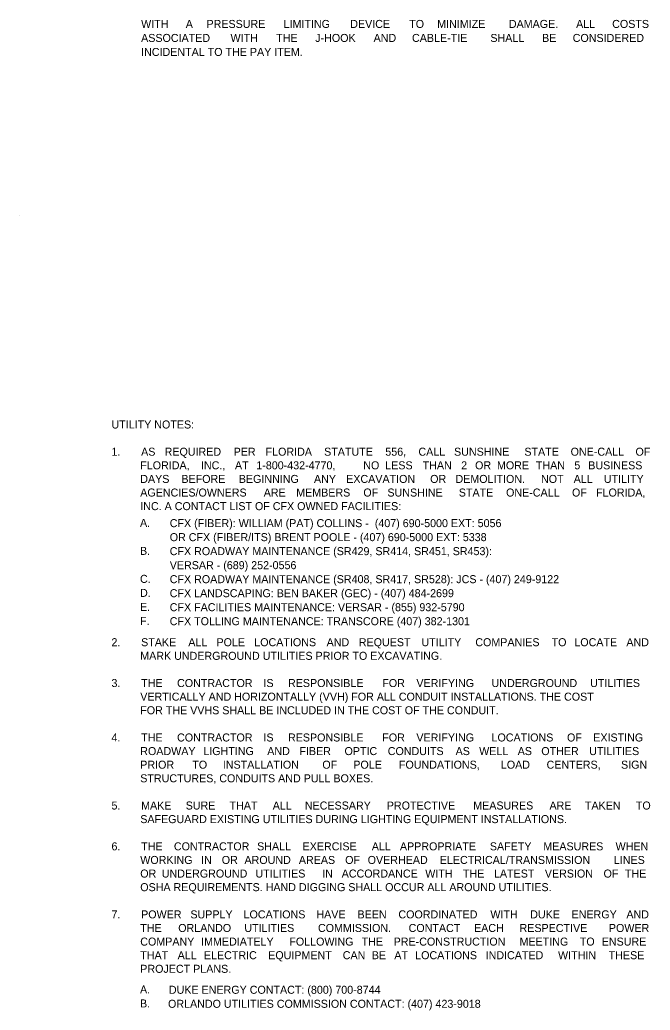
# Model space of a CAD drawing. Extents: x -55 to 2471539, y -90 to 3608906.
# Drawn here: x -54 to 497, y 1661 to 2527 of the extents above; entities that cross this region are included whole.
import ezdxf

# ---------------------------------------------------------------- set-up
doc = ezdxf.new("R2010")
doc.units = 0
doc.layers.add('TextMinor', color=7, linetype='Continuous')
doc.layers.add('XSCell', color=7, linetype='Continuous')

msp = doc.modelspace()

# ---------------------------------------------------------------- linework, layer by layer
at = {"layer": 'TextMinor'}
msp.add_line((-54.3, 2356.32), (-54.3, 2356.32), dxfattribs=at)

# ---------------------------------------------------------------- texts
at = {"layer": 'XSCell'}
for s, p in [('WITH ', (51.88, 2519.99)), ('A ', (90.93, 2519.99)), ('PRESSURE ', (109.08, 2519.99)), ('LIMITING ', (176.56, 2519.99)), ('DEVICE ', (234.88, 2519.99)), ('TO ', (286.48, 2519.99)), ('MINIMIZE ', (310.96, 2519.99)), ('DAMAGE. ', (373.67, 2519.99)), (' ALL ', (429.95, 2519.99)), ('COSTS ', (464.09, 2519.99)), ('ASSOCIATED ', (51.88, 2507.74)), ('WITH ', (130.12, 2507.74)), ('THE ', (170.05, 2507.74)), ('J-HOOK ', (204.23, 2507.74)), ('AND ', (255.31, 2507.74)), ('CABLE-TIE ', (288.95, 2507.74)), ('SHALL ', (357.49, 2507.74)), ('BE ', (402.75, 2507.74)), ('CONSIDERED ', (429.56, 2507.74)), ('INCIDENTAL TO THE PAY ITEM.', (51.88, 2495.49)), ('UTILITY NOTES:', (25.93, 2169.7)), ('1.', (25.93, 2145.9)), ('AS ', (51.88, 2145.9)), ('REQUIRED ', (72.45, 2145.9)), ('PER ', (132.84, 2145.9)), ('FLORIDA ', (160.8, 2145.9)), ('STATUTE ', (212.02, 2145.9)), ('556, ', (265.56, 2145.9)), ('CALL ', (294.55, 2145.9)), ('SUNSHINE ', (325.71, 2145.9)), ('STATE ', (387.26, 2145.9)), ('ONE-CALL ', (427.72, 2145.9)), ('OF ', (484.48, 2145.9)), ('FLORIDA, ', (51.12, 2134)), ('INC., ', (104.23, 2134)), ('AT ', (133.98, 2134)), ('1-800-432-4770, ', (152.68, 2134)), ('NO ', (246.28, 2134)), ('LESS ', (265.49, 2134)), ('THAN ', (298.24, 2134)), ('2 ', (331.94, 2134)), ('OR ', (344.13, 2134)), ('MORE ', (363.28, 2134)), ('THAN ', (397.29, 2134)), ('5 ', (430.99, 2134)), ('BUSINESS ', (443.18, 2134)), ('DAYS ', (51.12, 2122.1)), ('BEFORE ', (87.13, 2122.1)), ('BEGINNING ', (137.34, 2122.1)), ('ANY ', (203.14, 2122.1)), ('EXCAVATION ', (231.32, 2122.1)), ('OR ', (304.81, 2122.1)), ('DEMOLITION. ', (326.96, 2122.1)), ('NOT ', (401.82, 2122.1)), ('ALL ', (430.4, 2122.1)), ('UTILITY ', (456.81, 2122.1)), ('AGENCIES/OWNERS ', (51.12, 2110.2)), ('ARE ', (159.16, 2110.2)), ('MEMBERS ', (187.58, 2110.2)), ('OF ', (246.33, 2110.2)), ('SUNSHINE ', (267.4, 2110.2)), ('STATE ', (329.87, 2110.2)), ('ONE-CALL ', (371.24, 2110.2)), ('OF ', (428.91, 2110.2)), ('FLORIDA, ', (449.99, 2110.2)), ('INC. A CONTACT LIST OF CFX OWNED FACILITIES:', (51.12, 2098.3)), ('A.', (50.92, 2083.7)), ('CFX (FIBER): WILLIAM (PAT) COLLINS -  (407) 690-5000 EXT: 5056', (76.93, 2083.43)), ('OR CFX (FIBER/ITS) BRENT POOLE - (407) 690-5000 EXT: 5338', (76.93, 2071.18)), ('B.', (50.92, 2059.2)), ('CFX ROADWAY MAINTENANCE (SR429, SR414, SR451, SR453): ', (76.93, 2058.93)), ('VERSAR - (689) 252-0556', (76.93, 2046.68)), ('C.', (50.92, 2034.7)), ('CFX ROADWAY MAINTENANCE (SR408, SR417, SR528): JCS - (407) 249-9122', (76.93, 2034.43)), ('D.', (50.92, 2022.45)), ('CFX LANDSCAPING: BEN BAKER (GEC) - (407) 484-2699', (76.93, 2022.18)), ('E.', (50.92, 2010.2)), ('CFX FACILITIES MAINTENANCE: VERSAR - (855) 932-5790', (76.93, 2009.93)), ('F.', (50.92, 1997.95)), ('CFX TOLLING MAINTENANCE: TRANSCORE (407) 382-1301', (76.93, 1997.68)), ('2.', (25.93, 1979.3)), ('STAKE ', (51.88, 1979.3)), ('ALL ', (93.17, 1979.3)), ('POLE ', (117.82, 1979.3)), ('LOCATIONS ', (150.88, 1979.3)), ('AND ', (214.2, 1979.3)), ('REQUEST ', (242.38, 1979.3)), ('UTILITY ', (297.2, 1979.3)), ('COMPANIES ', (344.33, 1979.3)), ('TO ', (411.09, 1979.3)), ('LOCATE ', (430.98, 1979.3)), ('AND ', (476.52, 1979.3)), ('MARK UNDERGROUND UTILITIES PRIOR TO EXCAVATING.', (51.12, 1967.4)), ('3.', (25.93, 1943.6)), ('THE ', (51.88, 1943.6)), ('CONTRACTOR ', (83.33, 1943.6)), ('IS ', (158.93, 1943.6)), ('RESPONSIBLE ', (180.41, 1943.6)), ('FOR ', (262.92, 1943.6)), ('VERIFYING ', (292.77, 1943.6)), ('UNDERGROUND ', (358.54, 1943.6)), ('UTILITIES ', (444.75, 1943.6)), ('VERTICALLY AND HORIZONTALLY (VVH) FOR ALL CONDUIT INSTALLATIONS. THE COST ', (51.12, 1931.7)), ('FOR THE VVHS SHALL BE INCLUDED IN THE COST OF THE CONDUIT.', (51.12, 1919.8)), ('4.', (25.93, 1896)), ('THE ', (51.88, 1896)), ('CONTRACTOR ', (83.33, 1896)), ('IS ', (158.92, 1896)), ('RESPONSIBLE ', (180.4, 1896)), ('FOR ', (262.91, 1896)), ('VERIFYING ', (292.75, 1896)), ('LOCATIONS ', (358.52, 1896)), ('OF ', (424.58, 1896)), ('EXISTING ', (447.54, 1896)), ('ROADWAY ', (51.12, 1884.1)), ('LIGHTING ', (106.3, 1884.1)), ('AND ', (162.24, 1884.1)), ('FIBER ', (190.41, 1884.1)), ('OPTIC ', (229.87, 1884.1)), ('CONDUITS ', (267.7, 1884.1)), ('AS ', (327.08, 1884.1)), ('WELL ', (347.7, 1884.1)), ('AS ', (381.42, 1884.1)), ('OTHER ', (402.04, 1884.1)), ('UTILITIES ', (444, 1884.1)), ('PRIOR ', (51.12, 1872.2)), ('TO ', (96.64, 1872.2)), ('INSTALLATION ', (123.39, 1872.2)), ('OF ', (210.46, 1872.2)), ('POLE ', (237.55, 1872.2)), ('FOUNDATIONS, ', (277.47, 1872.2)), ('LOAD ', (366.67, 1872.2)), ('CENTERS, ', (406.69, 1872.2)), ('SIGN ', (471.85, 1872.2)), ('STRUCTURES, CONDUITS AND PULL BOXES.', (51.12, 1860.3)), ('5.', (25.93, 1836.5)), ('MAKE ', (51.88, 1836.5)), ('SURE ', (90.88, 1836.5)), ('THAT ', (129.25, 1836.5)), ('ALL ', (167.06, 1836.5)), ('NECESSARY ', (195.14, 1836.5)), ('PROTECTIVE ', (266.87, 1836.5)), ('MEASURES ', (342.5, 1836.5)), ('ARE ', (409.22, 1836.5)), ('TAKEN ', (440.22, 1836.5)), ('TO ', (484.81, 1836.5)), ('SAFEGUARD EXISTING UTILITIES DURING LIGHTING EQUIPMENT INSTALLATIONS.', (51.12, 1824.6)), ('6.', (25.93, 1800.8)), ('THE ', (51.88, 1800.8)), ('CONTRACTOR ', (80.56, 1800.8)), ('SHALL ', (153.39, 1800.8)), ('EXERCISE ', (193.15, 1800.8)), ('ALL ', (253.73, 1800.8)), ('APPROPRIATE ', (278.35, 1800.8)), ('SAFETY ', (357.05, 1800.8)), ('MEASURES ', (403.81, 1800.8)), ('WHEN ', (467.07, 1800.8)), ('WORKING ', (51.12, 1788.9)), ('IN ', (104.36, 1788.9)), ('OR ', (122.44, 1788.9)), ('AROUND ', (142.3, 1788.9)), ('AREAS ', (189.9, 1788.9)), ('OF ', (230.43, 1788.9)), ('OVERHEAD ', (250.13, 1788.9)), ('ELECTRICAL/TRANSMISSION ', (313.25, 1788.9)), ('LINES ', (465.57, 1788.9)), ('OR ', (51.12, 1777)), ('UNDERGROUND ', (69.97, 1777)), ('UTILITIES ', (151.91, 1777)), ('IN ', (210.32, 1777)), ('ACCORDANCE ', (227.4, 1777)), ('WITH ', (300.52, 1777)), ('THE ', (333.46, 1777)), ('LATEST ', (360.64, 1777)), ('VERSION ', (405.17, 1777)), ('OF ', (456.54, 1777)), ('THE ', (475.23, 1777)), ('OSHA REQUIREMENTS. HAND DIGGING SHALL OCCUR ALL AROUND UTILITIES.', (51.12, 1765.1)), ('7.', (25.93, 1741.3)), ('POWER ', (51.88, 1741.3)), ('SUPPLY ', (95, 1741.3)), ('LOCATIONS ', (141.53, 1741.3)), ('HAVE ', (205.24, 1741.3)), ('BEEN ', (241.22, 1741.3)), ('COORDINATED ', (277.03, 1741.3)), ('WITH ', (357.5, 1741.3)), ('DUKE ', (392.36, 1741.3)), ('ENERGY ', (428.57, 1741.3)), ('AND ', (476.52, 1741.3)), ('THE ', (51.12, 1729.4)), ('ORLANDO ', (84.35, 1729.4)), ('UTILITIES ', (142.2, 1729.4)), ('COMMISSION. ', (206.65, 1729.4)), ('CONTACT ', (285.96, 1729.4)), ('EACH ', (343.21, 1729.4)), ('RESPECTIVE ', (383.03, 1729.4)), ('POWER ', (461.2, 1729.4)), ('COMPANY ', (51.12, 1717.5)), ('IMMEDIATELY ', (104.38, 1717.5)), ('FOLLOWING ', (181.58, 1717.5)), ('THE ', (244.82, 1717.5)), ('PRE-CONSTRUCTION ', (272.86, 1717.5)), ('MEETING ', (383.03, 1717.5)), ('TO ', (435.74, 1717.5)), ('ENSURE ', (454.94, 1717.5)), ('THAT ', (51.12, 1705.6)), ('ALL ', (83.84, 1705.6)), ('ELECTRIC ', (106.84, 1705.6)), ('EQUIPMENT ', (163.06, 1705.6)), ('CAN ', (228.33, 1705.6)), ('BE ', (253.73, 1705.6)), ('AT ', (273.43, 1705.6)), ('LOCATIONS ', (291.71, 1705.6)), ('INDICATED ', (353.38, 1705.6)), ('WITHIN ', (416.73, 1705.6)), ('THESE ', (461.02, 1705.6)), ('PROJECT PLANS.', (51.12, 1693.7)), ('A.', (50.92, 1675.64)), ('DUKE ENERGY CONTACT: (800) 700-8744', (76.18, 1675.37)), ('B.', (50.92, 1663.39)), ('ORLANDO UTILITIES COMMISSION CONTACT: (407) 423-9018', (75.42, 1663.12))]:
    msp.add_text(s, height=7, dxfattribs=at).set_placement(p)

doc.saveas('drawing.dxf')
